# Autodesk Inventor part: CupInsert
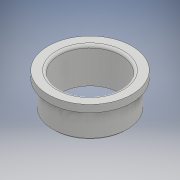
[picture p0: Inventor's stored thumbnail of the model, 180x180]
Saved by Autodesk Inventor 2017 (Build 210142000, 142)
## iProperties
Created: 2016-12
Part Number: CupInsert
Material: Generic
Document SubType Name: Modeling
Designer: Dans
Density: 1 g/cm^3
Appearance: Default
Author: Dans
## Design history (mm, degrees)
sketch "Sketch1"
  geometry: L1 (41.5, -30)-(41.5, 0) reference; L2 (-41.5, -30)-(-41.5, 0) reference; L3 (-44.653, -30)-(44.653, -30) reference; L4 (41.4, 0)-(41.4, -30); L5 (32.5, -30)-(34, 0); L6 (41.4, -30)-(32.5, -30); L7 (0, -30)-(0, 0); L8 (46.5, 0)-(-46.5, 0) reference; L9 (41.4, 0)-(46.5, 0); L10 (41.4, 0)-(46.5, 0); L11 (46.5, 0)-(46.5, 8); L12 (46.5, 8)-(34.4, 8); L13 (34.4, 8)-(33.992, -0.157)
  constraints: 22 end point, 4 vertical, 3 collinear, 3 point on line, 1 horizontal, 1 midpoint, 1 perpendicular, 4 other
  dimensions: "d0" = 7.5 distance of L1.end L5.end; "d1" = 7.4 distance of L5.end L4.start
revolve "Revolution1" sketch "Sketch1" stored, may be unused: angle "d3" = 90 deg
fillet "Fillet3" dims "d8" = 3
chamfer "Chamfer1" distance "d9" = 2; stored, may be unused: second distance "d10" = 2, angle "d11" = 45 deg
body "Solid1"
node "Reference1"
node "Reference2"
